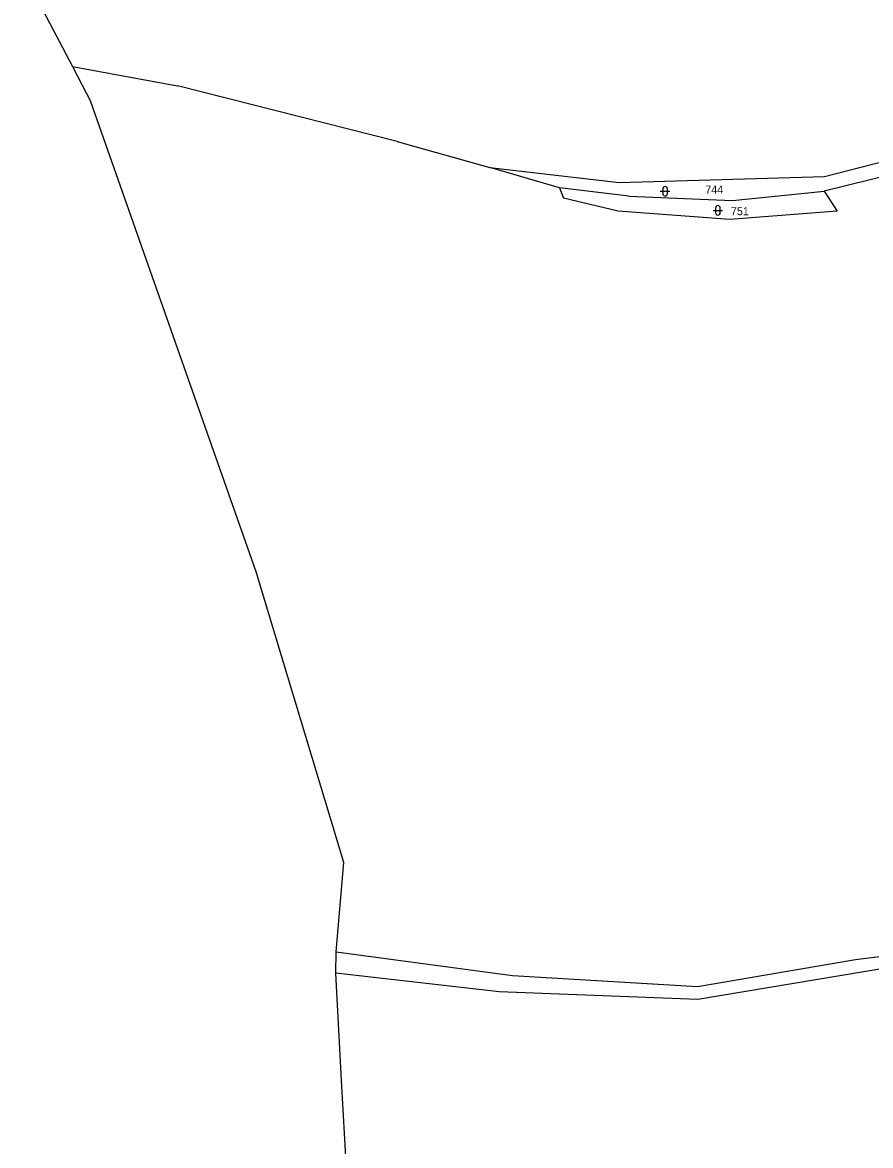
# Model space of a CAD drawing. Extents: x -754970 to -752637, y -970569 to -968179.
# Drawn here: x -754572.8 to -754392.6, y -970155.3 to -969916.8 of the extents above; entities that cross this region are included whole.
import ezdxf
from ezdxf.enums import TextEntityAlignment as Align

# ---------------------------------------------------------------- set-up
doc = ezdxf.new("R2010")
doc.units = 0
doc.header["$LTSCALE"] = 0.68
doc.layers.add('1', color=7, linetype='Continuous', lineweight=25)
doc.layers.add('3', color=7, linetype='Continuous', lineweight=25)
doc.layers.add('2', color=7, linetype='Continuous')

msp = doc.modelspace()

# ---------------------------------------------------------------- linework, layer by layer
at = {"layer": '1'}
for p, q in [((-754572.75, -969905.84), (-754562.12, -969926.14)), ((-754562.12, -969926.14), (-754558.21, -969933.61)), ((-754562.12, -969926.14), (-754539.83, -969930.21)), ((-754493.12, -969942.05), (-754539.83, -969930.21)), ((-754523.12, -970033.42), (-754558.21, -969933.61)), ((-754493.12, -969942.05), (-754473.47, -969947.58)), ((-754402.32, -969949.46), (-754380.05, -969943.77)), ((-754458.68, -969951.86), (-754473.47, -969947.58)), ((-754378.81, -969946.81), (-754402.4, -969952.57)), ((-754443.89, -969953.66), (-754458.68, -969951.86)), ((-754458.68, -969951.86), (-754457.82, -969954.05)), ((-754443.89, -969953.66), (-754421.93, -969954.59)), ((-754421.93, -969954.59), (-754402.4, -969952.57)), ((-754402.4, -969952.57), (-754399.67, -969956.85)), ((-754446.22, -969956.85), (-754457.82, -969954.05)), ((-754422.48, -969958.64), (-754446.22, -969956.85)), ((-754399.67, -969956.85), (-754422.48, -969958.64)), ((-754504.49, -970095.22), (-754523.12, -970033.42)), ((-754506.09, -970114.2), (-754504.49, -970095.22)), ((-754506.14, -970118.68), (-754506.09, -970114.2)), ((-754506.09, -970114.2), (-754468.62, -970119.2)), ((-754429.34, -970121.54), (-754395.77, -970115.78)), ((-754395.77, -970115.78), (-754384.57, -970114.38)), ((-754381.2, -970116.27), (-754429.26, -970124.26)), ((-754471.46, -970122.67), (-754506.14, -970118.68)), ((-754468.62, -970119.2), (-754429.34, -970121.54)), ((-754429.26, -970124.26), (-754471.46, -970122.67))]:
    msp.add_line(p, q, dxfattribs=at)
for points in [[(-754473.47, -969947.58), (-754445.99, -969950.77), (-754402.32, -969949.46)], [(-754503.93, -970160.19), (-754504.95, -970141.47), (-754506.14, -970118.68)]]:
    msp.add_lwpolyline(points, dxfattribs=at)
at = {"layer": '3'}
for p, q in [((-754437.231, -969952.621), (-754435.229, -969952.621)), ((-754436.731, -969952.121), (-754436.731, -969953.122)), ((-754435.729, -969953.122), (-754435.729, -969952.121)), ((-754425.511, -969956.171), (-754425.511, -969957.172)), ((-754424.509, -969957.172), (-754424.509, -969956.171)), ((-754426.011, -969956.671), (-754424.009, -969956.671))]:
    msp.add_line(p, q, dxfattribs=at)
for centre, start, end in [((-754436.23, -969952.1209), 0, 180), ((-754436.23, -969953.1209), 180, 359.98789), ((-754425.01, -969956.1709), 0, 180), ((-754425.01, -969957.1709), 180, 359.98789)]:
    msp.add_arc(centre, 0.5, start, end, dxfattribs=at)

# ---------------------------------------------------------------- texts
at = {"layer": '2'}
for s, p in [('744', (-754425.779, -969953.115)), ('751', (-754420.339, -969957.695))]:
    msp.add_text(s, height=1.7, dxfattribs=at).set_placement(p, align=Align.CENTER)

doc.saveas('drawing.dxf')
